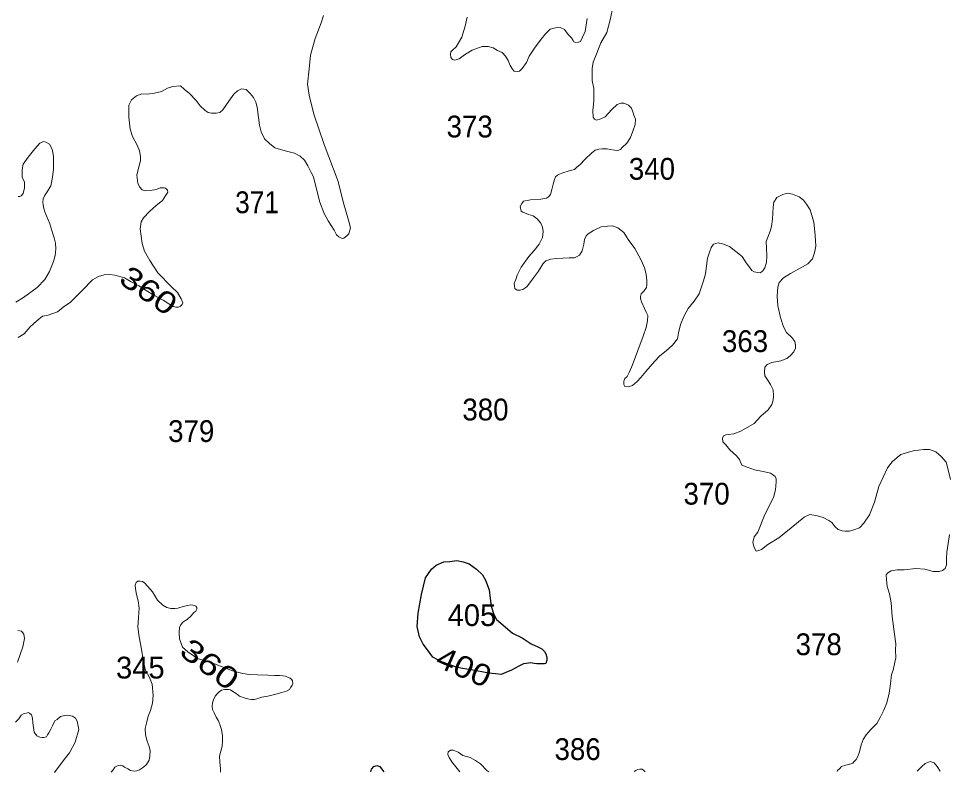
# Model space of a CAD drawing. Extents: x 445.4 to 500, y 8728.7 to 8784.
# Drawn here: x 457.68 to 464.5, y 8728.69 to 8734.23 of the extents above; entities that cross this region are included whole.
import ezdxf
from ezdxf.enums import TextEntityAlignment as Align

# ---------------------------------------------------------------- set-up
doc = ezdxf.new("R2010")
doc.units = 0
doc.header["$LTSCALE"] = 0.064
doc.layers.add('1', color=7, linetype='Continuous', lineweight=25)
doc.layers.add('2', color=7, linetype='Continuous', lineweight=13)
doc.layers.add('21', color=7, linetype='Continuous')
doc.layers.add('61', color=7, linetype='Continuous')

msp = doc.modelspace()

# ---------------------------------------------------------------- linework, layer by layer
at = {"layer": '1'}
msp.add_lwpolyline([(460.7178, 8729.5386), (460.6775, 8729.5923), (460.6472, 8729.6325), (460.6203, 8729.6863), (460.6035, 8729.7635), (460.6102, 8729.8608), (460.6338, 8729.9984), (460.664, 8730.1193), (460.7078, 8730.183), (460.7414, 8730.2132), (460.7986, 8730.2367), (460.8423, 8730.2401), (460.8927, 8730.2468), (460.9398, 8730.2367), (460.9835, 8730.2233), (461.0373, 8730.183), (461.0811, 8730.1428), (461.1046, 8730.1025), (461.1315, 8730.032), (461.1382, 8729.9682), (461.145, 8729.9111), (461.1651, 8729.8507), (461.1853, 8729.8138), (461.2492, 8729.7601), (461.303, 8729.7131), (461.3736, 8729.6795), (461.4409, 8729.6359), (461.488, 8729.6124), (461.5183, 8729.599), (461.5384, 8729.5788), (461.5485, 8729.5621), (461.5552, 8729.5386), (461.5552, 8729.5151), (461.5485, 8729.4916), (461.5384, 8729.4882), (461.5149, 8729.4882), (461.4813, 8729.4882), (461.4611, 8729.4916), (461.4375, 8729.4949), (461.4039, 8729.4916), (461.3837, 8729.4882), (461.3501, 8729.4714), (461.2963, 8729.4412), (461.2526, 8729.4244), (461.2189, 8729.411), (461.1786, 8729.4144), (461.1281, 8729.4211), (461.0003, 8729.4446), (460.9364, 8729.4546), (460.8894, 8729.4647), (460.849, 8729.4781), (460.7885, 8729.5016), (460.7548, 8729.5184)], close=True, dxfattribs=at)
msp.add_lwpolyline([(460.2618, 8728.6946), (460.2682, 8728.7154), (460.2851, 8728.7357), (460.3051, 8728.7424), (460.3273, 8728.7344), (460.3408, 8728.7185), (460.3509, 8728.705), (460.3566, 8728.6947)], dxfattribs=at)
at = {"layer": '2'}
for points in [[(462.0344, 8734.2857), (462.0211, 8734.2166), (461.9945, 8734.1236)], [(459.9203, 8733.3016), (459.843, 8733.5248), (459.8084, 8733.6647), (459.7977, 8733.7444), (459.8084, 8733.856), (459.819, 8733.957), (459.8536, 8734.0793), (459.8963, 8734.1953), (459.9149, 8734.2485)], [(460.9704, 8734.2353), (460.9545, 8734.1689), (460.9305, 8734.0891), (460.9068, 8734.0479), (460.8882, 8734.0187), (460.8615, 8733.9947), (460.8509, 8733.9814), (460.8482, 8733.9655), (460.8509, 8733.9389), (460.8615, 8733.9256), (460.8775, 8733.9203), (460.9121, 8733.931), (460.9494, 8733.9602), (461.0053, 8733.9947), (461.0799, 8734.0213), (461.1251, 8734.0213), (461.1597, 8734.0107), (461.1917, 8733.9921), (461.2263, 8733.9761), (461.2503, 8733.9496), (461.2716, 8733.9177), (461.2849, 8733.8805), (461.3035, 8733.8539), (461.3142, 8733.8406), (461.3381, 8733.8379), (461.3541, 8733.8406), (461.3727, 8733.8592), (461.4047, 8733.9044), (461.426, 8733.9496), (461.4633, 8734.008), (461.5138, 8734.0745), (461.5458, 8734.1143), (461.5804, 8734.1489), (461.6177, 8734.1568), (461.6363, 8734.1622), (461.6523, 8734.1595), (461.6843, 8734.1462), (461.7109, 8734.109), (461.7348, 8734.0851), (461.7482, 8734.0638), (461.7535, 8734.0559), (461.7668, 8734.0505), (461.7881, 8734.0532), (461.8014, 8734.0585), (461.8174, 8734.0904), (461.836, 8734.1303), (461.8507, 8734.2272)], [(461.9945, 8734.1236), (461.9519, 8734.0465), (461.9226, 8733.9721), (461.896, 8733.9057), (461.8881, 8733.8583), (461.8881, 8733.7706), (461.8988, 8733.7121), (461.8988, 8733.6244), (461.8935, 8733.5474), (461.8961, 8733.5022), (461.9041, 8733.4863), (461.9201, 8733.4809), (461.952, 8733.4889), (461.984, 8733.5049), (462.0319, 8733.558), (462.0719, 8733.5952), (462.0985, 8733.6058), (462.1198, 8733.6058), (462.1544, 8733.5899), (462.1757, 8733.5686), (462.1863, 8733.5421), (462.1943, 8733.5155), (462.205, 8733.4863), (462.2023, 8733.4491), (462.1863, 8733.3986), (462.1704, 8733.3534), (462.1411, 8733.3109), (462.1087, 8733.2803), (462.0954, 8733.2643), (462.0768, 8733.2563), (462.0528, 8733.259), (462.0209, 8733.2643), (461.9969, 8733.2696), (461.9623, 8733.2696), (461.9357, 8733.267), (461.909, 8733.259), (461.8824, 8733.2377), (461.8372, 8733.1926), (461.7972, 8733.1527), (461.7759, 8733.1341), (461.7573, 8733.1181), (461.72, 8733.1075), (461.6721, 8733.0942), (461.6481, 8733.0836), (461.6321, 8733.0756), (461.6188, 8733.065), (461.6108, 8733.0437), (461.6002, 8733.0092), (461.5922, 8732.972), (461.5815, 8732.9348), (461.5682, 8732.9162), (461.5523, 8732.9082), (461.5097, 8732.9002), (461.4351, 8732.8949), (461.3845, 8732.8843), (461.3704, 8732.8693), (461.359, 8732.845), (461.3659, 8732.8125), (461.3781, 8732.804), (461.4191, 8732.7886), (461.4537, 8732.778), (461.483, 8732.7567), (461.5097, 8732.7229), (461.523, 8732.6936), (461.5283, 8732.6617), (461.523, 8732.6192), (461.499, 8732.5687), (461.4618, 8732.5236), (461.4218, 8732.4784), (461.3659, 8732.4013), (461.3366, 8732.3429), (461.326, 8732.311), (461.3153, 8732.2817), (461.318, 8732.2631), (461.3207, 8732.2445), (461.3286, 8732.2366), (461.3366, 8732.2312), (461.3579, 8732.2312), (461.3792, 8732.2366), (461.4085, 8732.2552), (461.4564, 8732.3216), (461.4937, 8732.3721), (461.5283, 8732.4279), (461.547, 8732.4465), (461.5842, 8732.4598), (461.6268, 8732.4651), (461.6721, 8732.4678), (461.72, 8732.4704), (461.7573, 8732.4704), (461.7733, 8732.4757), (461.7946, 8732.489), (461.8132, 8732.5209), (461.8265, 8732.5687), (461.8319, 8732.6033), (461.8425, 8732.6299), (461.8585, 8732.6458), (461.8984, 8732.6697), (461.9543, 8732.6963), (461.9996, 8732.7016), (462.0369, 8732.7043), (462.0768, 8732.6883)], [(458.6697, 8732.1956), (458.7363, 8732.1584), (458.7789, 8732.1318), (458.8108, 8732.1132), (458.8295, 8732.1079), (458.8508, 8732.1079), (458.8614, 8732.1132), (458.8774, 8732.1265), (458.8827, 8732.1397), (458.8694, 8732.169), (458.8428, 8732.2142), (458.7975, 8732.2567), (458.699, 8732.3603), (458.6404, 8732.4507), (458.6005, 8732.5171), (458.5819, 8732.5756), (458.5686, 8732.6811), (458.5766, 8732.7343), (458.5926, 8732.7635), (458.6379, 8732.8087), (458.6858, 8732.8539), (458.7311, 8732.8911), (458.7577, 8732.9283), (458.771, 8732.9522), (458.7683, 8732.9655), (458.755, 8732.9814), (458.7444, 8732.9841), (458.7151, 8732.9841), (458.6885, 8732.9708), (458.6405, 8732.9628), (458.6086, 8732.9602), (458.582, 8732.9681), (458.5633, 8732.9894), (458.55, 8733.0186), (458.5447, 8733.0771), (458.5607, 8733.1462), (458.5714, 8733.1824), (458.5714, 8733.2142), (458.5634, 8733.2541), (458.5474, 8733.2966), (458.5128, 8733.3604), (458.4941, 8733.4136), (458.4862, 8733.5013), (458.4861, 8733.5901), (458.5048, 8733.63), (458.5421, 8733.6592), (458.5793, 8733.6725), (458.6193, 8733.6699), (458.6725, 8733.6778), (458.7258, 8733.6911), (458.7684, 8733.715), (458.8083, 8733.7283), (458.8642, 8733.731), (458.8909, 8733.7071), (458.9308, 8733.6752), (458.9787, 8733.6247), (459.008, 8733.5848), (459.0453, 8733.5503), (459.0666, 8733.537), (459.0932, 8733.5317), (459.1252, 8733.5317), (459.1544, 8733.537), (459.1757, 8733.5556), (459.2183, 8733.6194), (459.2556, 8733.6699), (459.2822, 8733.6964), (459.3115, 8733.7097), (459.3461, 8733.7044), (459.3754, 8733.6752), (459.3994, 8733.6459), (459.418, 8733.6114), (459.4287, 8733.5742), (459.4367, 8733.4998), (459.4447, 8733.444), (459.458, 8733.3935), (459.4819, 8733.343), (459.5192, 8733.3085), (459.5565, 8733.2766), (459.6323, 8733.2536), (459.7016, 8733.2377), (459.7442, 8733.2164), (459.7761, 8733.1872), (459.8001, 8733.1447), (459.824, 8733.0968), (459.84, 8733.0649), (459.864, 8732.9746), (459.8879, 8732.8789), (459.9199, 8732.7939), (459.9492, 8732.7407), (459.9921, 8732.6728), (460.0107, 8732.6383), (460.0267, 8732.6223), (460.0507, 8732.6117), (460.064, 8732.6143), (460.0853, 8732.6303), (460.1012, 8732.6462), (460.1119, 8732.6887), (460.0986, 8732.7446), (460.0586, 8732.8801), (460.0214, 8733.0289), (459.9203, 8733.3016)], [(457.6719, 8732.9184), (457.6852, 8732.9184), (457.6932, 8732.9237), (457.7091, 8732.9423), (457.7198, 8732.9822), (457.7198, 8733.0247), (457.7011, 8733.0619), (457.7011, 8733.1177), (457.7091, 8733.1576), (457.7464, 8733.2081), (457.7943, 8733.2692), (457.8325, 8733.3123), (457.8592, 8733.3229), (457.8751, 8733.3176), (457.9018, 8733.3043), (457.9231, 8733.2671), (457.9311, 8733.2166), (457.9311, 8733.1183), (457.9231, 8733.0465), (457.9124, 8732.9987), (457.8858, 8732.9535), (457.8645, 8732.9243), (457.8565, 8732.903), (457.8538, 8732.8791), (457.8565, 8732.8579), (457.8618, 8732.8313), (457.8672, 8732.8074), (457.9048, 8732.718), (457.9261, 8732.6462), (457.9367, 8732.617), (457.9474, 8732.5771), (457.95, 8732.5346), (457.9447, 8732.4868), (457.9314, 8732.4416), (457.9021, 8732.3699), (457.8675, 8732.3114), (457.8111, 8732.251), (457.7126, 8732.1792), (457.654, 8732.1447)], [(462.0768, 8732.6883), (462.1194, 8732.6564), (462.1514, 8732.6033), (462.202, 8732.5368), (462.2312, 8732.4837), (462.2499, 8732.4465), (462.2712, 8732.396), (462.2845, 8732.3482), (462.2898, 8732.303), (462.2898, 8732.2711), (462.2872, 8732.2525), (462.2685, 8732.2259), (462.2472, 8732.2047), (462.2419, 8732.1861), (462.2419, 8732.1701), (462.2499, 8732.1462), (462.2719, 8732.0967), (462.2852, 8732.0702), (462.2959, 8732.0462), (462.2932, 8732.0064), (462.2852, 8731.9585), (462.2613, 8731.8948), (462.224, 8731.7885), (462.1841, 8731.6848), (462.16, 8731.6274), (462.144, 8731.5981), (462.128, 8731.5822), (462.12, 8731.5636), (462.12, 8731.5397), (462.128, 8731.5237), (462.1547, 8731.5211), (462.1839, 8731.5317), (462.2186, 8731.5609), (462.2452, 8731.5902), (462.2825, 8731.6354), (462.3464, 8731.7071), (462.3836, 8731.7496), (462.4316, 8731.7868), (462.4768, 8731.8293), (462.5141, 8731.8745), (462.5227, 8731.919), (462.536, 8731.9801), (462.5627, 8732.0439), (462.5919, 8732.097), (462.6372, 8732.1502), (462.6745, 8732.206), (462.7064, 8732.3016), (462.7198, 8732.3521), (462.7357, 8732.4664), (462.749, 8732.5116), (462.7624, 8732.5448), (462.7784, 8732.5687), (462.813, 8732.5793), (462.8449, 8732.5714), (462.8955, 8732.5528), (462.9434, 8732.5156), (462.9887, 8732.4784), (463.018, 8732.4332), (463.042, 8732.4013), (463.0606, 8732.3774), (463.0766, 8732.3667), (463.1032, 8732.3614), (463.1218, 8732.3588), (463.1298, 8732.3641), (463.1405, 8732.3747), (463.1564, 8732.396), (463.1671, 8732.4385), (463.1698, 8732.481), (463.1671, 8732.5395), (463.1644, 8732.59), (463.1777, 8732.6219), (463.1937, 8732.6644), (463.2044, 8732.6989), (463.2124, 8732.7521), (463.2177, 8732.8424), (463.223, 8732.877), (463.2443, 8732.9115), (463.2879, 8732.9337), (463.3214, 8732.9448), (463.3577, 8732.9365), (463.4079, 8732.917), (463.4386, 8732.8919), (463.4609, 8732.864), (463.4888, 8732.8223), (463.5167, 8732.7303), (463.5251, 8732.6356), (463.5307, 8732.5548), (463.521, 8732.5066), (463.5052, 8732.4623), (463.4703, 8732.4243), (463.4163, 8732.3926), (463.3434, 8732.3546), (463.2926, 8732.323), (463.2609, 8732.2881), (463.2514, 8732.2533), (463.2451, 8732.1868), (463.2514, 8732.1172), (463.2704, 8732.0317), (463.2926, 8731.9621), (463.3148, 8731.9209), (463.3531, 8731.8844)], [(457.6727, 8731.8842), (457.7153, 8731.9108), (457.7605, 8731.9639), (457.8084, 8732.0065), (457.851, 8732.041), (457.8936, 8732.049), (457.9602, 8732.0729), (458.0028, 8732.1075), (458.0561, 8732.1447), (458.1439, 8732.2324), (458.2171, 8732.3072), (458.2624, 8732.3311), (458.305, 8732.3444), (458.3449, 8732.347), (458.3822, 8732.3417), (458.4541, 8732.3231), (458.502, 8732.2939), (458.5579, 8732.2646), (458.6111, 8732.2301), (458.6697, 8732.1956)], [(463.3531, 8731.8844), (463.3753, 8731.8559), (463.3817, 8731.8274), (463.3817, 8731.8052), (463.369, 8731.7799), (463.3436, 8731.7514), (463.3182, 8731.7293), (463.2738, 8731.7134), (463.2072, 8731.7008), (463.1723, 8731.685), (463.1565, 8731.666), (463.1533, 8731.6311), (463.1565, 8731.6026), (463.1755, 8731.5741), (463.1977, 8731.5393), (463.2163, 8731.5), (463.2194, 8731.4557), (463.2163, 8731.4241), (463.2067, 8731.3924), (463.1814, 8731.3544), (463.1274, 8731.3069), (463.0767, 8731.2531), (462.9784, 8731.1961), (462.9275, 8731.1763), (462.8863, 8731.1731), (462.8704, 8731.1699), (462.8514, 8731.1636), (462.845, 8731.1446), (462.8482, 8731.1193), (462.8704, 8731.0971), (462.899, 8731.0591), (462.9465, 8731.0148), (462.9687, 8730.9895), (462.9878, 8730.9483), (463.0258, 8730.9325), (463.0797, 8730.9135), (463.1432, 8730.9008), (463.1966, 8730.8889), (463.213, 8730.8787), (463.232, 8730.8629), (463.2383, 8730.847), (463.2392, 8730.8251), (463.2352, 8730.7661), (463.2194, 8730.7091), (463.1559, 8730.5856), (463.1052, 8730.4558), (463.0766, 8730.421), (463.0671, 8730.3799), (463.0766, 8730.3419), (463.0925, 8730.3166), (463.1115, 8730.3197), (463.1306, 8730.3292), (463.1781, 8730.364), (463.2574, 8730.4147), (463.3875, 8730.5192), (463.4446, 8730.5666), (463.4858, 8730.5856), (463.5429, 8730.5761), (463.5841, 8730.5635), (463.6254, 8730.5413), (463.6476, 8730.5255), (463.6729, 8730.4938), (463.6951, 8730.4748), (463.7237, 8730.4653), (463.7459, 8730.4622), (463.7776, 8730.4622), (463.8093, 8730.4717), (463.8506, 8730.4875), (463.8823, 8730.5223), (463.9235, 8730.5825), (463.9616, 8730.6743), (463.9933, 8730.7914), (464.0567, 8730.9275), (464.0916, 8730.9719), (464.1265, 8731.0035), (464.1551, 8731.0257), (464.2043, 8731.0393), (464.2455, 8731.052), (464.2836, 8731.0583), (464.3216, 8731.0614), (464.366, 8731.0614), (464.4104, 8731.0456), (464.4517, 8731.0108), (464.4866, 8730.9696), (464.5024, 8730.9127), (464.5183, 8730.843)], [(464.5119, 8730.4378), (464.5024, 8730.3729), (464.4929, 8730.3096), (464.4897, 8730.2589), (464.4897, 8730.2146), (464.4802, 8730.1893), (464.4612, 8730.1735)], [(464.4612, 8730.1735), (464.4358, 8730.1671), (464.3914, 8730.1671), (464.331, 8730.1826), (464.2645, 8730.1893), (464.1789, 8730.1798), (464.1287, 8730.178), (464.0837, 8730.1703), (464.0583, 8730.1576), (464.0456, 8730.1418), (464.0488, 8730.107), (464.0552, 8730.0563), (464.071, 8730.0025), (464.0825, 8729.9353), (464.0899, 8729.8368), (464.1086, 8729.7063), (464.1169, 8729.6358), (464.1143, 8729.5908), (464.1184, 8729.5329), (464.1101, 8729.4999), (464.0977, 8729.442), (464.0853, 8729.411), (464.0791, 8729.3407), (464.0687, 8729.2725), (464.0509, 8729.2026), (464.0299, 8729.1475), (464.0036, 8729.095), (463.9773, 8729.0504), (463.9352, 8729.0058), (463.901, 8728.9664), (463.8774, 8728.9323), (463.8642, 8728.8929), (463.8511, 8728.843), (463.8378, 8728.8076), (463.8273, 8728.7866), (463.8115, 8728.7709), (463.801, 8728.7604), (463.78, 8728.7525), (463.7511, 8728.7446), (463.7195, 8728.7341), (463.7037, 8728.7184), (463.6906, 8728.7053), (463.6865, 8728.6988)], [(458.3564, 8728.6922), (458.3696, 8728.7095), (458.3828, 8728.731), (458.406, 8728.7425), (458.4225, 8728.7441), (458.4406, 8728.7408), (458.4538, 8728.731), (458.4786, 8728.7178), (458.4968, 8728.7046), (458.5232, 8728.6996), (458.543, 8728.7029), (458.5645, 8728.7112), (458.5925, 8728.7293), (458.614, 8728.7507), (458.6338, 8728.782), (458.6404, 8728.8134), (458.6421, 8728.8496), (458.6338, 8728.8826), (458.619, 8728.9205), (458.6074, 8728.9666), (458.6041, 8729.0128), (458.6173, 8729.0639), (458.6272, 8729.1034), (458.644, 8729.1457), (458.6588, 8729.2), (458.6638, 8729.2561), (458.6573, 8729.3397), (458.637, 8729.3888), (458.6052, 8729.4466), (458.5907, 8729.5188), (458.5791, 8729.5968), (458.5618, 8729.6864), (458.5502, 8729.7566), (458.556, 8729.8288), (458.5618, 8729.8982), (458.5531, 8729.9502), (458.5412, 8729.9971), (458.5348, 8730.0402), (458.5316, 8730.0658), (458.538, 8730.085), (458.5508, 8730.0945), (458.5684, 8730.0961), (458.5844, 8730.0929), (458.602, 8730.0802), (458.6228, 8730.0578), (458.658, 8730.0179), (458.6964, 8729.9572), (458.7348, 8729.9205), (458.7636, 8729.9029), (458.794, 8729.8949), (458.8228, 8729.8949), (458.8452, 8729.8981), (458.8836, 8729.9093), (458.9188, 8729.9157), (458.9364, 8729.9221), (458.9556, 8729.9205), (458.9668, 8729.9173), (458.978, 8729.9109), (458.9844, 8729.9013), (458.9844, 8729.8901), (458.978, 8729.8758), (458.962, 8729.8662), (458.9428, 8729.8422), (458.9124, 8729.8151), (458.8804, 8729.7943), (458.8652, 8729.7735), (458.858, 8729.7544), (458.8548, 8729.7177), (458.8564, 8729.6729), (458.8802, 8729.6116), (458.9186, 8729.5761), (458.9897, 8729.5289), (459.114, 8729.4875), (459.2472, 8729.4373), (459.3212, 8729.4166), (459.3708, 8729.4114), (459.4295, 8729.4088), (459.5065, 8729.4061), (459.5561, 8729.4035), (459.5914, 8729.4022), (459.6162, 8729.4009), (459.6357, 8729.397), (459.6501, 8729.3918), (459.6684, 8729.3827), (459.6788, 8729.3749), (459.6879, 8729.3632), (459.6906, 8729.3449), (459.684, 8729.3319), (459.6749, 8729.3176), (459.6658, 8729.3006), (459.6423, 8729.2889), (459.6083, 8729.2785), (459.564, 8729.2655), (459.5052, 8729.2524), (459.4609, 8729.2433), (459.4256, 8729.2316), (459.406, 8729.2264), (459.3852, 8729.2264), (459.3682, 8729.229), (459.3382, 8729.2368), (459.2977, 8729.2524)], [(457.6665, 8729.5019), (457.7058, 8729.6146), (457.7189, 8729.6749), (457.7145, 8729.7056), (457.697, 8729.7275), (457.6706, 8729.7341)], [(459.2977, 8729.2524), (459.2729, 8729.272), (459.2494, 8729.285), (459.2325, 8729.298), (459.2181, 8729.2993), (459.2011, 8729.3006), (459.1868, 8729.2993), (459.1646, 8729.2941), (459.1476, 8729.2837), (459.1346, 8729.2681), (459.1202, 8729.2511), (459.1059, 8729.2238), (459.0994, 8729.2016), (459.0966, 8729.1788), (459.1006, 8729.1527), (459.1123, 8729.128), (459.1253, 8729.0967), (459.1436, 8729.0694), (459.1567, 8729.0368), (459.1645, 8729.0068), (459.1723, 8728.9612), (459.1737, 8728.9225), (459.1693, 8728.8833), (459.1606, 8728.8485), (459.1519, 8728.8115), (459.154, 8728.7659), (459.1584, 8728.7202), (459.1584, 8728.6932)], [(457.9385, 8728.6916), (458.0093, 8728.7852), (458.0481, 8728.8354), (458.0907, 8728.9128), (458.1178, 8729.0056), (458.1062, 8729.0675), (458.0925, 8729.0903), (458.0702, 8729.1042), (458.034, 8729.1125), (458.0117, 8729.1098), (457.9839, 8729.1014), (457.9588, 8729.0792), (457.9417, 8729.0695), (457.9256, 8729.0341), (457.9127, 8729.0084), (457.8966, 8728.9827), (457.8869, 8728.9666), (457.8805, 8728.9537), (457.8611, 8728.9473), (457.8483, 8728.9473), (457.8321, 8728.9505), (457.8096, 8728.9602), (457.7903, 8728.9859), (457.7838, 8729.0212), (457.7806, 8729.0566), (457.7774, 8729.0888), (457.7709, 8729.1145), (457.7548, 8729.1273), (457.7452, 8729.1306), (457.7323, 8729.1273), (457.7162, 8729.1241), (457.6936, 8729.1113), (457.6775, 8729.0855), (457.6522, 8729.0604)], [(460.9157, 8728.6954), (460.857, 8728.7686), (460.8376, 8728.8009), (460.8268, 8728.8225), (460.8311, 8728.8419), (460.8484, 8728.8549), (460.8657, 8728.8549), (460.9024, 8728.8398), (460.937, 8728.816), (460.9911, 8728.8009), (461.0321, 8728.7793), (461.0667, 8728.7556), (461.1143, 8728.706), (461.1278, 8728.6957)], [(464.2753, 8728.6995), (464.3066, 8728.7334), (464.3341, 8728.7581), (464.3699, 8728.7718), (464.4002, 8728.7608), (464.4223, 8728.7361), (464.4431, 8728.6997)], [(462.1971, 8728.697), (462.2082, 8728.7044), (462.2236, 8728.7121), (462.237, 8728.716), (462.2543, 8728.716), (462.2659, 8728.7063), (462.2755, 8728.6986), (462.2766, 8728.6971)]]:
    msp.add_lwpolyline(points, dxfattribs=at)

# ---------------------------------------------------------------- texts
at = {"layer": '21'}
for s, width, p in [('373', 0.95, (460.8187, 8733.3532)), ('371', 0.9, (459.2659, 8732.797)), ('363', 0.95, (462.8407, 8731.7776)), ('380', 0.95, (460.9344, 8731.2757)), ('379', 0.95, (458.7737, 8731.1171)), ('370', 0.95, (462.5585, 8730.6576)), ('378', 0.95, (463.3815, 8729.5521)), ('386', 0.95, (461.6114, 8728.7824))]:
    msp.add_text(s, height=0.16, dxfattribs=dict(at, width=width)).set_placement(p)
at = {"layer": '21', "width": 0.95}
msp.add_text('340', height=0.16, dxfattribs=at).set_placement((462.4961, 8733.0428), align=Align.RIGHT)
at = {"layer": '21'}
msp.add_text('405', height=0.16, dxfattribs=at).set_placement((460.8262, 8729.7659))
msp.add_text('345', height=0.16, dxfattribs=at).set_placement((458.7478, 8729.3807), align=Align.RIGHT)
at = {"layer": '61'}
for s, rotation, width, p in [('360', 325.157, 1.25, (458.5849, 8732.1638)), ('360', 323.343, 1.3, (459.0318, 8729.4221)), ('400', 336.153, 1.15, (460.9139, 8729.3925))]:
    msp.add_text(s, height=0.16, rotation=rotation, dxfattribs=dict(at, width=width)).set_placement(p, align=Align.CENTER)

doc.saveas('drawing.dxf')
